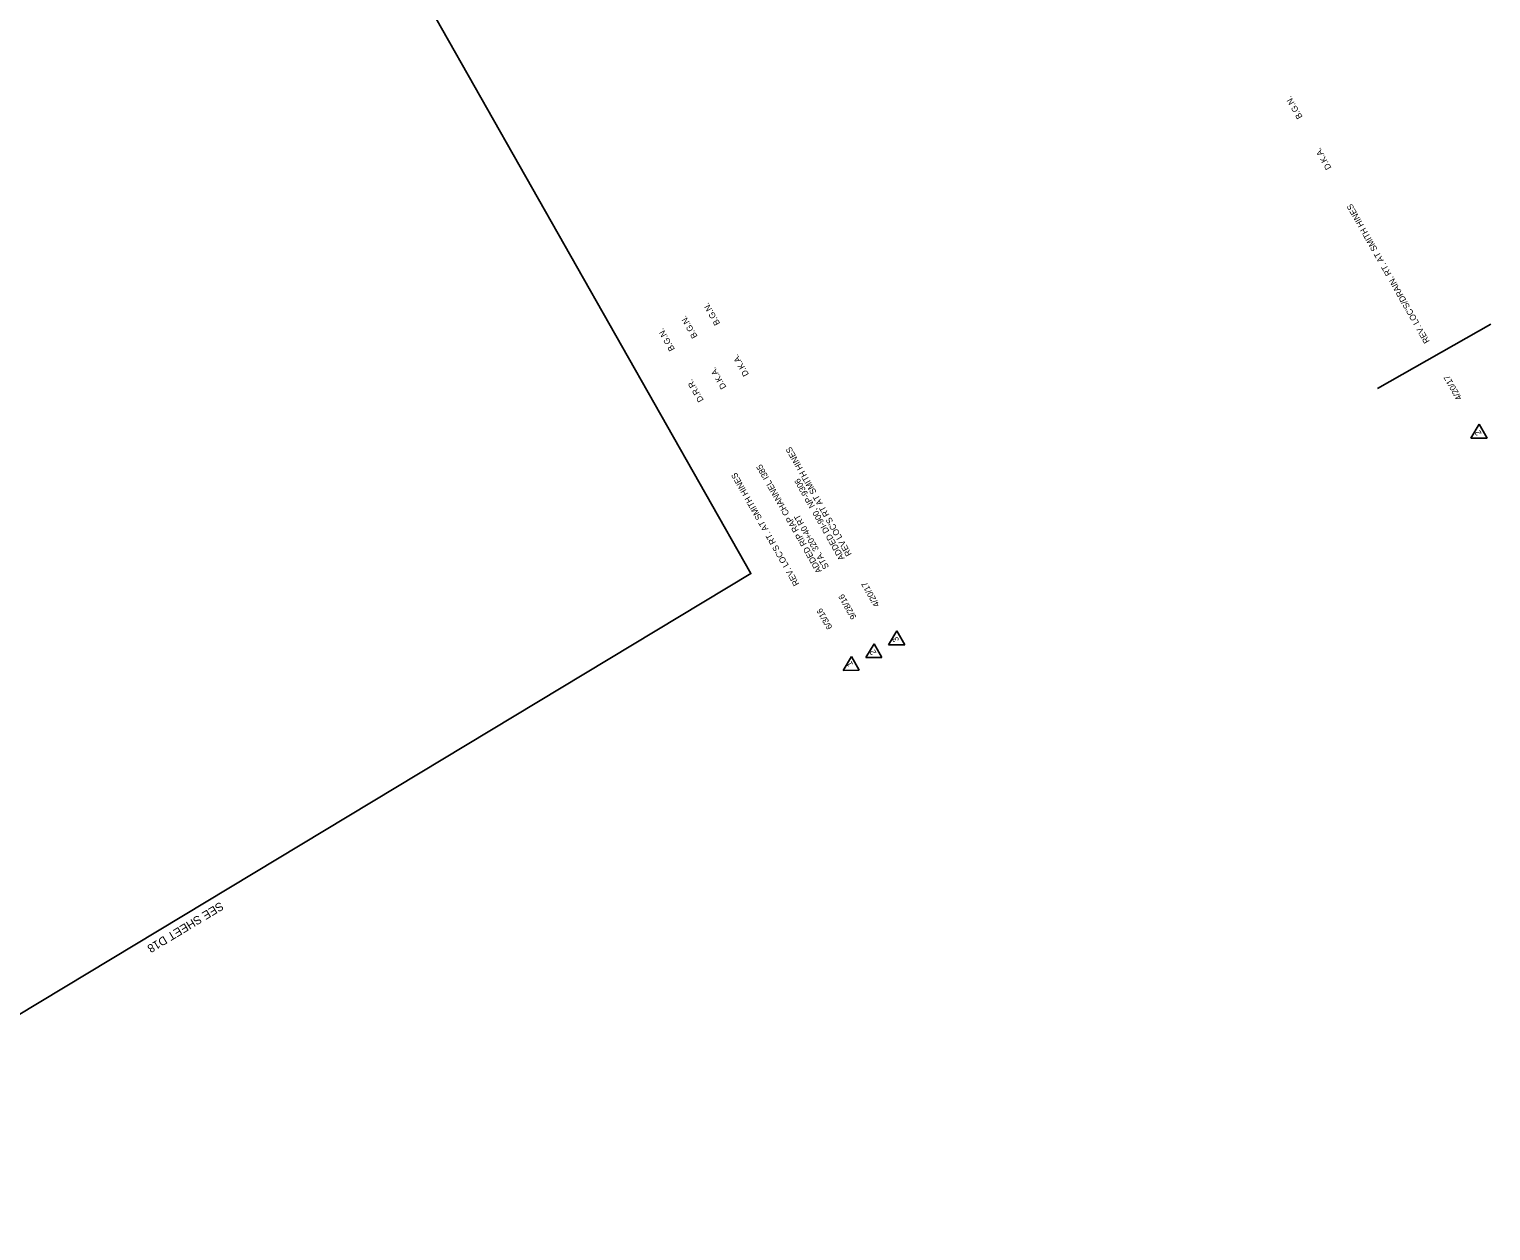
# Model space of a CAD drawing. Extents: x 1612558 to 1614658, y 1085653 to 1087522.
# Drawn here: x 1613608 to 1614658, y 1085653 to 1086516 of the extents above; entities that cross this region are included whole.
import ezdxf

# ---------------------------------------------------------------- set-up
doc = ezdxf.new("R2010")
doc.units = 0
for name, color, linetype in [('RD_EX_DR_Pipe', 7, 'Continuous'), ('RD_EX_Fence_Other', 7, 'Continuous'), ('RD_HC_Data', 7, 'Continuous')]:
    doc.layers.add(name, color=color, linetype=linetype)

msp = doc.modelspace()

# ---------------------------------------------------------------- linework, layer by layer
at = {"layer": 'RD_EX_DR_Pipe'}
for p, q in [((1614657.7, 1086304.1), (1614576.4, 1086258)), ((1614643.4, 1086222.2), (1614649.5, 1086232.2)), ((1614655.1, 1086222.3), (1614649.5, 1086232.2)), ((1614643.4, 1086222.2), (1614655.1, 1086222.3)), ((1614208.9, 1086064.6), (1614214.9, 1086074.6)), ((1614220.5, 1086064.7), (1614214.9, 1086074.6)), ((1614225.1, 1086073.8), (1614231.1, 1086083.8)), ((1614236.8, 1086073.9), (1614231.1, 1086083.8)), ((1614192.6, 1086055.4), (1614198.6, 1086065.4)), ((1614204.2, 1086055.5), (1614198.6, 1086065.4)), ((1614208.9, 1086064.6), (1614220.5, 1086064.7)), ((1614225.1, 1086073.8), (1614236.8, 1086073.9)), ((1614192.6, 1086055.4), (1614204.2, 1086055.5))]:
    msp.add_line(p, q, dxfattribs=at)
at = {"layer": 'RD_HC_Data'}
msp.add_lwpolyline([(1613343.7, 1085653.3), (1614126.4, 1086125), (1613415.2, 1087379), (1613116.7, 1087245.1), (1612843.1, 1087121.9), (1612576.5, 1087002), (1612672.7, 1086832.1), (1612642.4, 1086814.9), (1613299.9, 1085652.9)], close=True, dxfattribs=at)
msp.add_lwpolyline([(1613343.7, 1085653.3), (1614126.4, 1086125), (1613415.2, 1087379), (1613116.7, 1087245.1), (1612843.1, 1087121.9), (1612576.5, 1087002), (1612672.7, 1086832.1), (1612642.4, 1086814.9), (1613299.9, 1085652.9)], close=True, dxfattribs=at)
msp.add_lwpolyline([(1613343.7, 1085653.3), (1614126.4, 1086125), (1613415.2, 1087379), (1613116.7, 1087245.1), (1612843.1, 1087121.9), (1612576.5, 1087002), (1612672.7, 1086832.1), (1612642.4, 1086814.9), (1613299.9, 1085652.9)], close=True, dxfattribs=at)
msp.add_lwpolyline([(1613343.7, 1085653.3), (1614126.4, 1086125), (1613415.2, 1087379), (1613116.7, 1087245.1), (1612843.1, 1087121.9), (1612576.5, 1087002), (1612672.7, 1086832.1), (1612642.4, 1086814.9), (1613299.9, 1085652.9)], close=True, dxfattribs=at)
msp.add_lwpolyline([(1613343.7, 1085653.3), (1614126.4, 1086125), (1613415.2, 1087379), (1613116.7, 1087245.1), (1612843.1, 1087121.9), (1612576.5, 1087002), (1612672.7, 1086832.1), (1612642.4, 1086814.9), (1613299.9, 1085652.9)], close=True, dxfattribs=at)
msp.add_lwpolyline([(1613343.7, 1085653.3), (1614126.4, 1086125), (1613415.2, 1087379), (1613116.7, 1087245.1), (1612843.1, 1087121.9), (1612576.5, 1087002), (1612672.7, 1086832.1), (1612642.4, 1086814.9), (1613299.9, 1085652.9)], close=True, dxfattribs=at)
msp.add_lwpolyline([(1613343.7, 1085653.3), (1614126.4, 1086125), (1613415.2, 1087379), (1613116.7, 1087245.1), (1612843.1, 1087121.9), (1612576.5, 1087002), (1612672.7, 1086832.1), (1612642.4, 1086814.9), (1613299.9, 1085652.9)], close=True, dxfattribs=at)

# ---------------------------------------------------------------- texts
at = {"layer": 'RD_EX_DR_Pipe'}
for s, p in [('B.G.N.', (1614522.7, 1086453)), ('D.K.A.', (1614543.4, 1086416.5)), ("REV. LOC'S/DRAIN. RT. AT SMITH HINES", (1614614, 1086291.8)), ('B.G.N.', (1614104.4, 1086304.7)), ('B.G.N.', (1614088.2, 1086295.4)), ('B.G.N.', (1614071.9, 1086286.2)), ('D.K.A.', (1614125.1, 1086268.1)), ('D.R.R.', (1614092.6, 1086249.6)), ('D.K.A.', (1614108.9, 1086258.9)), ('4/20/17', (1614637.2, 1086250.9)), ('2', (1614651.3, 1086225.6)), ("REV LOC'S RT AT SMITH HINES", (1614198.9, 1086138.9)), ('ADDED RIP RAP CHANNEL I385', (1614177.5, 1086126.8)), ("REV. LOC'S RT. AT SMITH HINES", (1614161.3, 1086117.6)), ('ADDED DI-900, NP-9306', (1614193.8, 1086136)), ('STA. 320+40 RT', (1614182.6, 1086129.7)), ('4/20/17', (1614218.9, 1086102.5)), ('9/28/16', (1614202.4, 1086093.6)), ('6/3/16', (1614185.1, 1086086.3)), ('3', (1614233, 1086077.2)), ('2', (1614216.7, 1086068)), ('1', (1614200, 1086059.6))]:
    msp.add_text(s, height=4.4, rotation=119.5163, dxfattribs=at).set_placement(p)
at = {"layer": 'RD_EX_Fence_Other'}
msp.add_text('SEE SHEET D18', height=6, rotation=211.1281, dxfattribs=at).set_placement((1613745.3, 1085889.4))

doc.saveas('drawing.dxf')
